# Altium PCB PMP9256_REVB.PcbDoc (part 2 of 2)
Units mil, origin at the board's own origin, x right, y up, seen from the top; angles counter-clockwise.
Board outline 5025 x 2070 mil, 4 copper layers (Top Layer, Signal Layer 1, Signal Layer 2, Bottom Layer), stack 61.2 mil thick; 115 components, 45 nets, 247 pads, 260 vias.
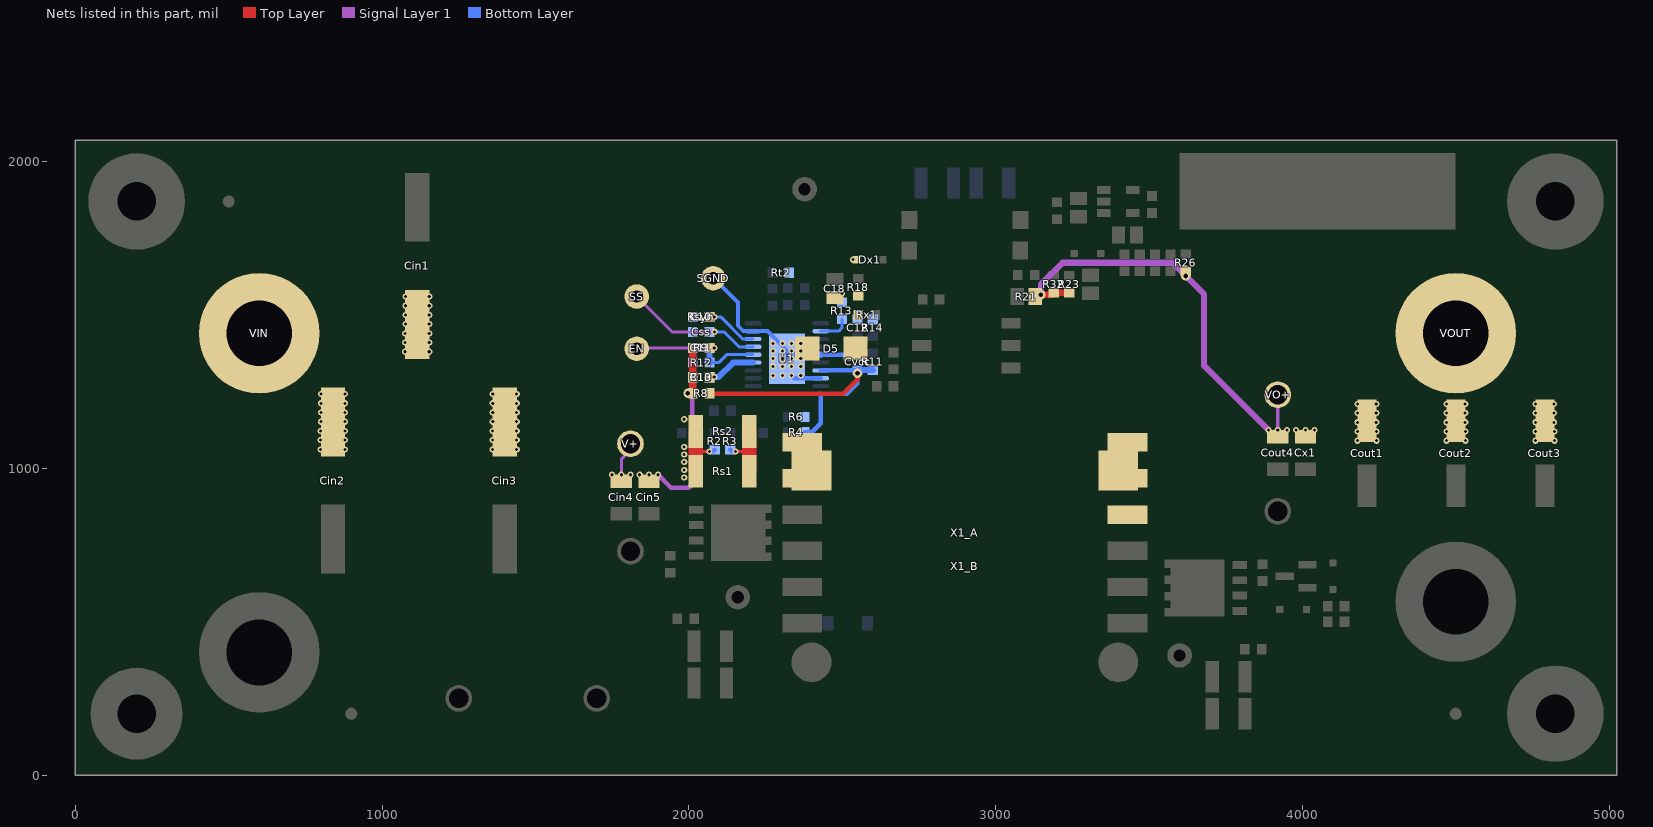
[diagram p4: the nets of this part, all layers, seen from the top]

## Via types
v1: diameter 20, hole 10, Top Layer to Bottom Layer, tented both sides, 252 vias
v2: diameter 30, hole 15, Top Layer to Bottom Layer, tented both sides, 8 vias

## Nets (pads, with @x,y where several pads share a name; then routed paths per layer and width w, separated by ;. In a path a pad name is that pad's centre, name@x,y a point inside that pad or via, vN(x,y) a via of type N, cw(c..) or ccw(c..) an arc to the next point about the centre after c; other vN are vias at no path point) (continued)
RS-: R3.2 Rs1.2 Rs2.2 X1_A.1 X1_A.2 X1_B.1 | length 181.7
  Top Layer w10: v1(2152,1055) 2196.61,1055
  Top Layer w47: Rs1.2@2196.61,990 2196.61,1055 Rs2.2@2196.61,1120
  Bottom Layer w15: R3.2@2135,1060 R3.2@2140,1055
SGND: C11.2 C12.2 C13.2 C18.2 Css.2 Cvcc.1 D5.2 Dx1.2 R6.1 R12.1 R13.1 R14.1 Rsyn.1 Rt2.1 SGND.1 U1.9 U1.15 U1.18 U1.21 | length 722
  Bottom Layer w12.5: SGND.1@2080,1620 2160,1540 2160,1464.6 2177.48,1447.13 U1.9@2209.76,1447.13 2256.17,1447.13 2320,1383.3 U1.21@2320,1357.56
  Bottom Layer w15: v1(2335,1302.56) 2343.98,1293.58 U1.18@2430.24,1293.58 ; U1.15@2430.44,1370.56 Cvcc.1@2550,1370.56
  Bottom Layer w20: U1.21@2335,1370.35 U1.15@2430.24,1370.35 U1.15@2430.44,1370.56
  other v1: 2275,1302.56 2305,1302.56 2365,1302.56 2275,1332.56 2305,1332.56 2335,1332.56 2365,1332.56 2275,1357.56 2305,1357.56 2335,1357.56 2365,1357.56 2275,1382.56 2305,1382.56 2335,1382.56 2365,1382.56 2275,1407.56 2305,1407.56 2335,1407.56 2365,1407.56 2500,1570 2535,1680
SLOPE: R13.2 U1.12 | length 101.9
  Bottom Layer w10: U1.12@2430.24,1447.13 2488.57,1447.13 2499.27,1457.83 R13.2@2499.27,1486.3
SS: Css.1 SS.1 U1.7 | length 464.2
  Signal Layer 1 w10: SS.1@1830,1560 1945.04,1444.96 v1(2084,1444.96)
  Bottom Layer w10: Css.1@2067.56,1444.96 v1(2084,1444.96) 2114.97,1444.96 2163.99,1395.94 U1.7@2209.76,1395.94
SYN/RT: C10.1 Rsyn.2 U1.8 | length 168.7
  Bottom Layer w10: Rsyn.2@2070.91,1493.56 2104,1493.56 2176.02,1421.54 U1.8@2209.76,1421.54
  other v1: 2084,1493.56
SYNC: U1.1
UVLO: C11.1 EN.1 R9.1 R12.2 U1.6 | length 469.6
  Signal Layer 1 w10: EN.1@1830,1390 1832.56,1392.56 v1(2083,1392.56)
  Bottom Layer w10: R12.2@2067.56,1344.56 2098,1344.56 2123.8,1370.35 U1.6@2209.76,1370.35 ; C11.1@2067.56,1392.56 v1(2083,1392.56)
  Bottom Layer w20: R12.2@2067.56,1344.56 C11.1@2067.56,1391.75
V+: Cin1.1 Cin2.1 Cin3.1 Cin4.1 Cin5.1 R2.2 R8.1 R9.2 R10.2 Rs1.1 Rs2.1 V+.1 VIN.1 | length 886.7
  Top Layer w10: 2023.39,1055 v1(2068,1055)
  Top Layer w25: R8.1@2012.44,1245 R10.2@2012.44,1296.56 R9.2@2012.44,1392.56
  Top Layer w47: Rs1.1@2023.39,990 2023.39,1055 Rs2.1@2023.39,1120
  Signal Layer 1 w10: v1(1780,979) 1780,1030 V+.1@1830,1080
  Signal Layer 1 w15: v1(1900,979) 1942,937 2000,937 2011,948 2011,1231 v2(1997,1245)
  Bottom Layer w15: R2.2@2080,1055 R2.2@2085,1060
  other v1: 1985,970 1750,979 1810,979 1840,979 1870,979 1985,995 1985,1020 1985,1045 800,1061.89 879,1061.89 1360,1061.89 1439,1061.89 1985,1070 800,1091.89 879,1091.89 1360,1091.89 1439,1091.89 800,1121.89 879,1121.89 1360,1121.89 1439,1121.89 801,1151.89 879,1151.89 1361,1151.89 1439,1151.89 1985.07,1160 801,1181.89 879,1181.89 1361,1181.89 1439,1181.89 801,1211.89 879,1211.89 1361,1211.89 1439,1211.89 801,1241.89 879,1241.89 1361,1241.89 1439,1241.89 1075,1380 1154,1380 1075,1410 1154,1410 1075,1440 1154,1440 1076,1470 1154,1470 1076,1500 1154,1500 1076,1530 1154,1530 1076,1560 1154,1560
VCC: Cvcc.2 D5.1 R4.2 R8.2 R11.2 R18.1 Rx1.2 U1.17 U1.20 | length 1031.3
  Top Layer w15: R8.2@2067.56,1245 2070.16,1242.4 2503.36,1242.4 2534.43,1273.47 2550,1289.04 v2(2550,1310)
  Bottom Layer w10: Cvcc.2@2550,1319.17 Cvcc.2@2550,1320
  Bottom Layer w13: U1.20@2430.24,1242.4 2515.84,1242.4 2550,1276.56 Cvcc.2@2550,1319.17
  Bottom Layer w15: R4.2@2377.56,1117.56 2401,1117.56 2430.24,1146.8 U1.20@2430.24,1242.4 ; U1.17@2430.24,1319.17 2534.43,1319.17 Cvcc.2@2550,1319.17
  Bottom Layer w20: Cvcc.2@2550,1320 R11.2@2600,1320
"VIN IC": C13.1 R10.1 U1.5 | length 157.8
  Bottom Layer w20: C13.1@2071.37,1297.89 2097.33,1297.89 2144.2,1344.76 U1.5@2209.76,1344.76
  other v1: 2083,1297.89
VOUT: Cout1.1 Cout2.1 Cout3.1 Cout4.1 Cx1.1 R21.2 R23.2 R26.2 R32.1 VO+.1 VOUT.1 X1_A.10 X1_A.11 X1_A.12 X1_B.4 | length 1396.3
  Top Layer w20: R21.2@3126.34,1573.31 3133.9,1565.75 v2(3147.81,1565.75) R32.1@3186.81,1565.75 ; R32.1@3190,1572.44 R23.2@3240,1572.44
  Signal Layer 1 w10: v1(3920,1124.5) VO+.1@3920,1240
  Signal Layer 1 w20: v2(3147.81,1565.75) 3147.81,1599.25 3218.56,1670 3577,1670 v2(3620,1627) 3680,1567 3680,1334.5 v1(3890,1124.5)
  other v1: 4180,1090 4242,1090 4470,1090 4532,1090 4760,1090 4822,1090 4180,1120 4242,1120 4470,1120 4532,1120 4760,1120 4822,1120 3950,1124.5 3980,1124.5 4010,1124.5 4040,1124.5 4180,1150 4241,1150 4470,1150 4531,1150 4760,1150 4821,1150 4180,1180 4241,1180 4470,1180 4531,1180 4760,1180 4821,1180 4180,1210 4241,1210 4470,1210 4531,1210 4760,1210 4821,1210
pads on no net: FID1.1 FID2.1 FID3.1 H1. H2. H3. H4. U3.1 U3.2 X2.2 X2.5

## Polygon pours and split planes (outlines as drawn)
SGND on Bottom Layer "Bottom Layer-SGND" (solid, pour order 22): 2070,1740 2575,1740 2640,1675 2640,1387.56 2400,1147.56 2050,1147.56 1980,1217.56 1980,1649.56
"ISO GND" on Bottom Layer "Bottom Layer-ISOGND" (solid, pour order 24): 5025,0 5025,2070 2960,2070 2960,0
PGND on Bottom Layer "Bottom Layer-PGND" (solid, remove dead copper, pour order 23): 0,2070 0,0 2840,0 2840,2070
Q1-D on Top Layer "Top Layer-Q1-D" (solid, pour order 30): 2840,900 2065,900 2065,0 2840,0
Q2-D on Top Layer "Top Layer-Q2-D" (solid, pour order 31): 3755,785 2960,785 2960,0 3755,0
RS- on Top Layer "Top Layer-RS-" (solid, pour order 27): 2840,1220 2840,910 2120,910 2120,1220
"ISO GND" on Top Layer "Top Layer-ISGND" (solid, pour order 35): 2960,2070 2960,1230.12 3553.12,1230.12 4043,1720 4685,1720 4870,1535 4870,1045 3890,1045 3765,920 3765,0 5025,0 5025,2070
VOUT on Top Layer "Top Layer-VOUT" (solid, pour order 29): 2960,1220 2960,795 3755,795 3755,925 3885,1055 4860.17,1055 4860.17,1529.83 4679.7,1710 4050,1710 3560,1220
V+ on Top Layer "Top Layer-VIN" (solid, pour order 26): 371,1551 371,910 2090,910 2090,1220 1760,1220 1270,1710 530,1710
PGND on Top Layer "Top Layer-PGND" (solid, pour order 33): 2840,2070 2840,1229.76 1765.24,1229.76 1275,1720 525,1720 360,1555 360,900 2055,900 2055,0 0,0 0,2070
VCC on Top Layer "Top Layer-VCC" (solid, pour order 36): 2570,1580 2530,1580 2530,1470 2500,1440 2500,1320 2510,1310 2520,1300 2550,1300 2570,1300 2590,1320 2590,1450 2570,1470
"ISO GND" on Signal Layer 2 "MidLayer2-ISOGND" (solid, pour order 21): 2960,0 5025,0 5025,2070 2960,2070
PGND on Signal Layer 2 "MidLayer2-PGND" (solid, pour order 20): 0,0 0,2070 2840,2070 2840,0
"ISO GND" on Signal Layer 1 "MidLayer1-ISGND" (solid, pour order 34): 2960,2070 2960,1230.12 3553.12,1230.12 4043,1720 4685,1720 4870,1535 4870,1045 3890,1045 3765,920 3765,785 2960,785 2960,0 5025,0 5025,2070
VOUT on Signal Layer 1 "MidLayer1-VOUT" (solid, pour order 28): 2960,1220 2960,795 3755,795 3755,925 3885,1055 4860.17,1055 4860.17,1529.83 4679.7,1710 4050,1710 3560,1220
V+ on Signal Layer 1 "MidLayer1-VIN" (solid, pour order 25): 370,1550 370,910 2840,910 2840,1220 1760,1220 1270,1710 530,1710
PGND on Signal Layer 1 "MidLayer1-PGND" (solid, pour order 32): 2840,2070 2840,1229.76 1765.24,1229.76 1275,1720 525,1720 360,1555 360,900 2840,900 2840,0 0,0 0,2070

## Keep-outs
Keep-Out Layer:
  the board outline again, w10
  text ".Layer_Name" at 577,-858.49 h60

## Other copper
Top Layer:
  pour cut-out: 2152,1038.37 2152,1071.63 2174,1071.63 2174,1038.37
  pour cut-out: 2068,1071.63 2068,1038.37 2046,1038.37 2046,1071.63
  pour cut-out: 360,910 360,900 2055,900 2055,0 2065,0 2065,900 2895,900 2895,0 2905,0 2905,785 3755,785 3755,0 3765,0 3765,920 3890,1045 4870,1045 4870,1055.02 3885,1055 3755,925 3755,795 2905,795 2905,1220 2895,1220 2895,910 2120,910 2120,1220 3560,1220 4050,1710 4679.7,1710 4860.17,1529.83 4860,1055 4870,1055 4870,1535 4685,1720 4043,1720 3553.43,1230.43 2905,1230 2905,2070 2895,2070 2895,1230.23 2110,1230 1765,1230 1275,1720 525,1720 360,1555 360,910 370,910 370,1550 530,1710 1270,1710 1760,1220 2100,1220 2100,910
  pour cut-out: 2135.69,1055 ccw(c2152,1055) 2152,1038.69 ccw(c2152,1055) 2168.31,1055 ccw(c2152,1055) 2152,1071.31 ccw(c2152,1055)
  pour cut-out: 2051.69,1055 ccw(c2068,1055) 2068,1038.69 ccw(c2068,1055) 2084.31,1055 ccw(c2068,1055) 2068,1071.31 ccw(c2068,1055)
  pour cut-out: 1760.46,1079.61 ccw(c1810.39,1079.61) 1810.39,1029.68 ccw(c1810.39,1079.61) 1860.32,1079.61 ccw(c1810.39,1079.61) 1810.39,1129.53 ccw(c1810.39,1079.61)
  pour cut-out: 1759.68,730.39 ccw(c1809.61,730.39) 1809.61,680.46 ccw(c1809.61,730.39) 1859.53,730.39 ccw(c1809.61,730.39) 1809.61,780.32 ccw(c1809.61,730.39)
  pour cut-out: 3870.07,1240 ccw(c3920,1240) 3920,1190.07 ccw(c3920,1240) 3969.93,1240 ccw(c3920,1240) 3920,1289.93 ccw(c3920,1240)
  pour cut-out: 3870.07,860 ccw(c3920,860) 3920,810.07 ccw(c3920,860) 3969.93,860 ccw(c3920,860) 3920,909.93 ccw(c3920,860)
  text ".CopyrightYear" at 4070,70 h60
  text "TI" at 4346,70 h60
  text "©" at 3953,66.48 h105
  text ".Layer_Name" at 577,-858.49 h60
Signal Layer 1:
  pour cut-out: 360,910 360,900 2895,900 2895,0 2905,0 2905,785 3765,785 3765,920 3890,1045 4870,1045 4870,1055.02 3885,1055 3755,925 3755,795 2905,795 2905,1220 3560,1220 4050,1710 4679.7,1710 4860.17,1529.83 4860,1055 4870,1055 4870,1535 4685,1720 4043,1720 3553,1230 1765,1230 1275,1720 525,1720 360,1555 360,910 370,910 370,1550 530,1710 1270,1710 1760,1220 2895,1220 2895,910
  pour cut-out: 2905,2070 2905,0 2895,0 2895,2070
  pour cut-out: 2051.69,1055 ccw(c2068,1055) 2068,1038.69 ccw(c2068,1055) 2084.31,1055 ccw(c2068,1055) 2068,1071.31 ccw(c2068,1055)
  pour cut-out: 1883.37,979 ccw(c1900,979) 1900,962.37 ccw(c1900,979) 1916.63,979 ccw(c1900,979) 1900,995.63 ccw(c1900,979)
  pour cut-out: 3936.11,1124.5 ccw(c3920,1124.5) 3920,1140.61 ccw(c3920,1124.5) 3903.89,1124.5 ccw(c3920,1124.5) 3920,1108.39 ccw(c3920,1124.5)
  pour cut-out: 3936.31,974.5 ccw(c3920,974.5) 3920,990.81 ccw(c3920,974.5) 3903.69,974.5 ccw(c3920,974.5) 3920,958.19 ccw(c3920,974.5)
  pour cut-out: 1760.46,1079.61 ccw(c1810.39,1079.61) 1810.39,1029.68 ccw(c1810.39,1079.61) 1860.32,1079.61 ccw(c1810.39,1079.61) 1810.39,1129.53 ccw(c1810.39,1079.61)
  pour cut-out: 1763.69,979 ccw(c1780,979) 1780,962.69 ccw(c1780,979) 1796.31,979 ccw(c1780,979) 1780,995.31 ccw(c1780,979)
  pour cut-out: 1763.69,831 ccw(c1780,831) 1780,814.69 ccw(c1780,831) 1796.31,831 ccw(c1780,831) 1780,847.31 ccw(c1780,831)
  pour cut-out: 1759.68,730.39 ccw(c1809.61,730.39) 1809.61,680.46 ccw(c1809.61,730.39) 1859.53,730.39 ccw(c1809.61,730.39) 1809.61,780.32 ccw(c1809.61,730.39)
  pour cut-out: 3870.07,1240 ccw(c3920,1240) 3920,1190.07 ccw(c3920,1240) 3969.93,1240 ccw(c3920,1240) 3920,1289.93 ccw(c3920,1240)
  pour cut-out: 3870.07,860 ccw(c3920,860) 3920,810.07 ccw(c3920,860) 3969.93,860 ccw(c3920,860) 3920,909.93 ccw(c3920,860)
Signal Layer 2:
  rectangle net PGND: 2220,1230 2423.73,1480
  rectangle net SGND: 2258,1265.16 2388,1452.16
  pour cut-out: 2895,2070 2905,2070 2905,0 2895,0
Bottom Layer:
  rectangle net ISO: 2840,1877 2960,1982
  pour cut-out: 2895,2070 2905,2070 2905,0 2895,0
  pour cut-out: 1970,1655 1970,1212.56 2045.14,1137.42 2400,1137.62 2400,1147.56 2050,1147.56 1980,1217.56 1980,1650 2070,1740 2575,1740 2640,1675 2640,1387.56 2400,1147.56 2400,1137.63 2650,1383.32 2650,1680 2580,1750 2065,1750
  pour cut-out: 2345,1515.56 2397.43,1515.56 2397.43,1415.56 2386,1415.56 2386,1506.83 2345,1506.83
  text ".Layer_Name" at 577,-858.49 h60

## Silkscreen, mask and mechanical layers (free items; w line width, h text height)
Top Overlay:
  text ".PRJ_Number" at 1500,1890 h60
  text ".PCB_Rev" at 2100,1890 h60
  text ".PRJ_Title" at 1800,60 h60
  text ".Layer_Name" at 577,-858.49 h60
Bottom Overlay:
  rectangle: 2410,830 2710,930
  text ".PRJ_Number" at 3377,851 h60
  text "-" at 2790,850 h60
  text ".PCB_Rev" at 2890,850 h60
  text "UL94V-0" at 119,495 h60 r270
  text "MADE IN U.S." at 4550,83 h60
  text ".Layer_Name" at 577,-858.49 h60
Top Paste:
  text ".Layer_Name" at 577,-858.49 h60
Bottom Paste:
  text ".Layer_Name" at 577,-858.49 h60
Top Solder:
  text ".Layer_Name" at 577,-858.49 h60
  text ".Layer_Name" at 577,-858.49 h60
Bottom Solder:
  text ".Layer_Name" at 577,-858.49 h60
Drill Guide:
  text ".Layer_Name" at 577,-858.49 h60
M1 Board Outline:
  the board outline again, w10
  text ".Layer_Name" at 577,-858.49 h60
M2 Board Dimensions:
  rectangle: 0,-275 125,-150
  rectangle: 125,-400 500,-275
  lines w7: 0,-275 1000,-275 ; 125,-400 125,-150 ; 250,-400 250,-150 ; 500,-400 500,-150 ; 750,-400 750,-150 ; 0,-400 1000,-400 1000,-150 0,-150 0,-400
  text ".Layer_Name" at 577,-858.49 h60
M3 3D STEP Top:
  text ".Layer_Name" at 577,-858.49 h60
M4 3D STEP Bottom:
  text ".Layer_Name" at 577,-858.49 h60
M5 Assembly Top:
  lines w10: -292,-930.17 6308,-930.17 ; -292,-726.83 6310,-726.83 ; -292,-523.5 -292,-1133.5 3713,-1133.5 6310,-1133.5 6310,-523.5 -291.5,-523.5 -291.5,-1133.5 1284,-1133.5 ; 2173,-1133.5 2173,-523.5 ; 3440,-726.83 3440,-523.5 ; 4280,-726.83 4280,-523.5 ; 4902,-1140 4902,-937.17
  text "COMPONENTS MARKED 'DNP' SHOULD NOT BE POPULATED." at 1153.5,-318.5 h60
  text "ASSEMBLY VARIANT:" at 1153,-434 h60
  text ".VariantName" at 2189,-434 h60
  text "PCB VIEWED FROM TOP SIDE" at -228.5,-655.67 h60
  text "BOARD #:" at 2248,-655.67 h60
  text ".PRJ_Number" at 2793.5,-655.67 h60
  text "REV:" at 3638,-655.67 h60
  text ".PCB_Rev" at 3929.5,-655.67 h60
  text "SVN REV:" at 4476,-655.67 h60
  text ".VersionControl_RevNumber" at 4982,-655.67 h60
  text "PLOT NAME =" at -228.5,-1064.34 h60
  text ".plot_File_Name" at 577,-1064.34 h60
  text "GENERATED    :" at 2250,-1064.34 h60
  text ".Print_Date" at 3119.5,-1064.34 h60
  text ".Print_Time" at 3848.5,-1064.34 h60
  text "TEXAS INSTRUMENTS" at 5113,-1064.34 h60
M6 Assembly Bottom:
  lines w10: -292.5,-727.33 6309.5,-727.33 ; -290.5,-930.67 6309.5,-930.67 ; 1115.5,-1140.5 1115.5,-937.67 ; 1737.5,-727.33 1737.5,-524 ; 2577.5,-727.33 2577.5,-524 ; 3844.5,-1134 3844.5,-524 ; 4733.5,-1134 6309,-1134 6309,-524 -292.5,-524 -292.5,-1134 2304.5,-1134 6309.5,-1134 6309.5,-524
  text "COMPONENTS MARKED 'DNP' SHOULD NOT BE POPULATED." at 6102,-318 h60
  text ".VariantName" at 5058,-434 h60
  text "ASSEMBLY VARIANT:" at 6097,-434 h60
  text ".VersionControl_RevNumber" at 1035.5,-656.17 h60
  text "SVN REV:" at 1541.5,-656.17 h60
  text ".PCB_Rev" at 2088,-656.17 h60
  text "REV:" at 2379.5,-656.17 h60
  text ".PRJ_Number" at 3224,-656.17 h60
  text "BOARD #:" at 3769.5,-656.17 h60
  text "PCB VIEWED FROM BOTTOM SIDE" at 6246,-656.17 h60
  text "TEXAS INSTRUMENTS" at 904.5,-1064.84 h60
  text ".Print_Time" at 2169,-1064.84 h60
  text ".Print_Date" at 2898,-1064.84 h60
  text "GENERATED    :" at 3767.5,-1064.84 h60
  text ".plot_File_Name" at 5440.5,-1064.84 h60
  text "PLOT NAME =" at 6246,-1064.84 h60
M9 Title Sheet:
  drawing of 57 lines, arcs and shapes, not listed
  text "1" at 739.84,8036.5 h70
  text "2" at 3235.5,8036.5 h70
  text "3" at 5724.84,8036.5 h70
  text "4" at 8231.51,8036.5 h70
  text "5" at 10730.5,8036.5 h70
  text "6" at 13235.5,8036.5 h70
  text "A" at -416.5,6893.5 h70
  text "A" at 14383.5,6893.5 h70
  text "B" at -416.5,4513.5 h70
  text "B" at 14383.5,4513.5 h70
  text "C" at -416.5,2138.5 h70
  text "C" at 14383.5,2138.5 h70
  text "PROJECT TITLE:" at 11343.5,277.5 h45
  text ".PRJ_Title" at 11393.5,144.17 h70
  text "DESIGNED FOR:" at 11343.5,-23.5 h45
  text ".PRJ_Customer" at 11393.5,-163.5 h70
  text "D" at -416.5,-231.5 h70
  text "D" at 14383.5,-231.5 h70
  text "FILE NAME:" at 11343.5,-323.5 h45
  text ".PCB_File_Name_No_Path" at 11393.5,-443.5 h70
  text "Texas Instruments (TI) and/or its licensors do not warrant the accuracy or completeness of this specification" at 6374,-605.34 h45
  text "ENGINEER:" at 11343.5,-613.5 h45
  text "LAYOUT BY:" at 12848.5,-613.5 h45
  text "or any information contained therein. TI and/or its licensors do not warrant that this design will meet" at 6329.01,-718 h45
  text ".PRJ_Engineer" at 11393.5,-768.49 h70
  text ".PCB_Layout" at 12899,-768.49 h70
  text "the specifications, will be suitable for your application or fit for any particular purpose, or will operate in" at 6329.01,-830.67 h45
  text ".Layer_Name" at 577,-858.49 h60
  text "ALTIUM DESIGNER VERSION:" at 12848.5,-923.5 h45
  text "an implementation. TI and/or its licensors do not warrant that the design is production worthy. You should" at 6329.01,-943.33 h45
  text "completely validate and test your design implementation to confirm the system functionality for your application." at 6374,-1056 h45
  text ".print_Scale" at 11393.5,-1056.83 h70
  text ".Application_BuildNumber" at 12899,-1056.83 h70
  text "1" at 739.84,-1263.5 h70
  text "2" at 3235.5,-1263.5 h70
  text "3" at 5724.84,-1263.5 h70
  text "4" at 8231.51,-1263.5 h70
  text "5" at 10730.5,-1263.5 h70
  text "6" at 13235.5,-1263.5 h70
M10 Fab Notes:
  drawing of 185 lines, arcs and shapes, not listed
  text "DESIGN INFORMATION" at 12381.02,5910 h60
  text "MIN. TRACK WIDTH:" at 11736.46,5730 h60
  text "8" at 12832.7,5730 h60
  text "MIL" at 12987.46,5730 h60
  text "MIN. CLEARANCE:" at 11736.46,5598 h60
  text "0.2" at 12772.7,5598 h60
  text "mm" at 12987.46,5598 h60
  text "MIN. VIA PAD SIZE:" at 11736.46,5466 h60
  text "20" at 12802.71,5466 h60
  text "MIL" at 12987.46,5466 h60
  text "0.05mm (2MIL)" at 12431.46,5324.29 h60
  text "MINIMUM ANNULAR RING" at 11407.23,5320 h60
  text "EXTERNAL" at 13139.46,5320 h60
  text "PER" at 11607.23,5202 h60
  text "IPC-D-275 CLASS 2 LEVEL C" at 11827.23,5202 h60
  text "MIL, HOLES" at 13315.46,5089.71 h60
  text "+/-" at 12923,5089 h60
  text "+/-" at 13777,5089 h60
  text "REGISTRATION TOLERANCES:" at 11407.23,5084 h60
  text "METAL" at 12607,5084 h60
  text "5" at 13183.2,5084 h60
  text "3" at 14016.2,5084 h60
  text "MIL" at 14132.46,5084 h60
  text "MATERIAL:" at 11332.46,4874.54 h60
  text "FR-4 High Tg" at 12318.9,4734.21 h60
  text "FR-408" at 11753.46,4725.64 h60
  text "OTHER" at 13241.46,4725.64 h60
  text "X" at 12160,4720 h60
  text "62 MIL (1.6mm) +/-10%" at 12073.56,4562.92 h60
  text "THICKNESS:" at 11407.23,4558.64 h60
  text "X" at 11945.4,4558.64 h60
  text "OTHER" at 13358.46,4558.64 h60
  text "TOLERANCE:" at 11407.23,4400.64 h60
  text "X" at 12246.53,4400.64 h60
  text "ANSI IPC-6012 TYPE 3 CLASS 2" at 12433.48,4400.64 h60
  text "OTHER +/-" at 12433.46,4244.64 h60
  text "BOW & TWIST:" at 11407.23,4087.64 h60
  text "X" at 12246.53,4087.64 h60
  text "ANSI IPC-6012 TYPE 3 CLASS 2" at 12433.48,4087.64 h60
  text "OTHER +/-" at 12433.46,3929.13 h60
  text "DRILLING:" at 11332.46,3790.64 h60
  text "REFERENCE:" at 11407.23,3673.64 h60
  text "X" at 12055.46,3673.64 h60
  text "AS SHOWN" at 12242.46,3673.64 h60
  text "X" at 12956.46,3673.64 h60
  text "NC_DRILL FILES" at 13093.46,3673.64 h60
  text "PTH MIN COPPER THICKNESS:" at 11407.23,3515.64 h60
  text "X" at 12757.46,3515.64 h60
  text "1MIL" at 12894.46,3515.64 h60
  text "OTHER" at 13391.46,3515.64 h60
  text "BOARD FINISH:" at 11332.46,3356.64 h60
  text "SILKSCREEN:" at 11487.68,3238.64 h60
  text "X" at 12436.46,3238.64 h60
  text "TOP" at 12562.46,3238.64 h60
  text "X" at 12946.46,3238.64 h60
  text "BOTTOM" at 13073.46,3238.64 h60
  text "SILKSCREEN COLOR:" at 11487.68,3071.64 h60
  text "X" at 12435.42,3071.64 h60
  text "WHITE" at 12562.46,3071.64 h60
  text "OTHER" at 13073.46,3071.64 h60
  text "SOLDER RESIST COLOR:" at 11487.68,2901.64 h60
  text "X" at 12055.42,2742.44 h60
  text "GREEN" at 12182.46,2742.44 h60
  text "BLUE" at 12773.46,2742.44 h60
  text "OTHER" at 13311.46,2742.44 h60
  text "IMMERSION GOLD (ENIG)" at 12393.46,2553.92 h60
  text "ENEPIG" at 13731,2550.64 h60
  text "SURFACE FINISH:" at 11332.46,2549.64 h60
  text "IMM. TIN/SILVER OR EQUIV" at 11662,2392.64 h60
  text "OTHER" at 13093.46,2392.64 h60
  text "X" at 11500,2390 h60
  text "ARRAY/PANEL:" at 11332.46,2213.64 h60
  text "X" at 12210,2210 h60
  text "CUT AND TRIM PER MECH LAYER 1" at 12393.46,2209.35 h60
  text "N.C. ROUTE" at 12393.46,2057.64 h60
  text "V. SCORE" at 13259.46,2057.64 h60
  text "CERTIFICATION:" at 11332.46,1920.64 h60
  text "MATERIALS AND WORKMANSHIP FOR ALL PCBS" at 12057.46,1920.64 h60
  text "TO MEET OR EXCEED THE REQUIREMENTS OF:" at 12057.46,1822.64 h60
  text "X" at 11683.96,1686.13 h60
  text "ANSI IPC-A-600F CLASS ->" at 11822.96,1686.13 h60
  text "X" at 13462.02,1686.13 h60
  text "2" at 13580.96,1686.14 h60
  text "1" at 13265.96,1684.64 h60
  text "3" at 13934.96,1684.64 h60
  text "X" at 11686.02,1526.64 h60
  text "UL 94V-0" at 11822.96,1526.64 h60
  text "X" at 12498.02,1526.64 h60
  text "RoHS" at 12634.96,1526.64 h60
  text "OTHER" at 13279.36,1526.64 h60
  text "PER ORDER" at 13676.42,1526.64 h60
  text "ADDITIONAL REQUIREMENTS:" at 11332.46,1385.64 h60
  text "MICROSECTION:" at 11407.23,1270.64 h60
  text "YES" at 12312.96,1270.64 h60
  text "REQUIRED" at 13174.46,1114.49 h60
  text "BARE BOARD ELEC. TEST:" at 11407.23,1111.64 h60
  text "NONE" at 12712.96,1111.64 h60
  text "PER ORDER" at 13766.46,1111.64 h60
  text "X" at 12590,1110 h60
  text "MANUFACTURER'S UL:" at 11407.23,954.64 h60
  text "RAIL" at 12572.96,950.35 h60
  text "METAL" at 13064.77,950.35 h60
  text "X" at 13440,950 h60
  text "SILK" at 13576.46,950.35 h60
  text ".Layer_Name" at 577,-858.49 h60
M11 Gerber Information:
  lines w10: -292,-930.17 6308,-930.17 ; -292,-726.83 6310,-726.83 ; -292,-523.5 -292,-1133.5 3713,-1133.5 6310,-1133.5 6310,-523.5 -291.5,-523.5 -291.5,-1133.5 1284,-1133.5 ; 2173,-1133.5 2173,-523.5 ; 3440,-726.83 3440,-523.5 ; 4280,-726.83 4280,-523.5 ; 4902,-1140 4902,-937.17
  text "ALL ARTWORK VIEWED FROM TOP SIDE" at -228.5,-655.67 h60
  text "BOARD #:" at 2248,-655.67 h60
  text ".PRJ_Number" at 2793.5,-655.67 h60
  text "REV:" at 3638,-655.67 h60
  text ".PCB_Rev" at 3929.5,-655.67 h60
  text "SVN REV:" at 4476,-655.67 h60
  text ".VersionControl_RevNumber" at 4982,-655.67 h60
  text "LAYER NAME =" at -228.5,-858.49 h60
  text "PLOT NAME =" at -228.5,-1064.34 h60
  text ".plot_File_Name" at 577,-1064.34 h60
  text "GENERATED    :" at 2250,-1064.34 h60
  text ".Print_Date" at 3119.5,-1064.34 h60
  text ".Print_Time" at 3848.5,-1064.34 h60
  text "TEXAS INSTRUMENTS" at 5113,-1064.34 h60
M12 Stackup:
  drawing of 295 lines, arcs and shapes, not listed
  text "Layer" at 9790.58,7830 h60
  text "Name" at 10200.49,7830 h60
  text "Material" at 11140.23,7830 h60
  text "Thickness" at 12000,7830 h60
  text "Constant" at 12649.83,7830 h60
  text "Board Layer Stack" at 13219.69,7830 h60
  text "1" at 9790.58,7710 h60
  text "Top Overlay" at 10200.49,7710 h60
  text "2" at 9790.58,7590 h60
  text "Top Solder" at 10200.49,7590 h60
  text "Solder Resist" at 11140.23,7590 h60
  text "0.40mil" at 12000,7590 h60
  text "3.5" at 12649.83,7590 h60
  text "3" at 9790.58,7470 h60
  text "Top Layer" at 10200.49,7470 h60
  text "Copper" at 11140.23,7470 h60
  text "1.40mil" at 12000,7470 h60
  text "4" at 9790.58,7350 h60
  text "Dielectric1" at 10200.49,7350 h60
  text "FR-4" at 11140.23,7350 h60
  text "10.00mil" at 12000,7350 h60
  text "4.8" at 12649.83,7350 h60
  text "5" at 9790.58,7230 h60
  text "Signal Layer 1" at 10200.49,7230 h60
  text "Copper" at 11140.23,7230 h60
  text "0.70mil" at 12000,7230 h60
  text "6" at 9790.58,7110 h60
  text "Dielectric 3" at 10200.49,7110 h60
  text "FR-4" at 11140.23,7110 h60
  text "37.00mil" at 12000,7110 h60
  text "4.2" at 12649.83,7110 h60
  text "7" at 9790.58,6990 h60
  text "Signal Layer 2" at 10200.49,6990 h60
  text "Copper" at 11140.23,6990 h60
  text "0.70mil" at 12000,6990 h60
  text "8" at 9790.58,6870 h60
  text "Dielectric 2" at 10200.49,6870 h60
  text "FR-4" at 11140.23,6870 h60
  text "10.00mil" at 12000,6870 h60
  text "4.2" at 12649.83,6870 h60
  text "9" at 9790.58,6750 h60
  text "Bottom Layer" at 10200.49,6750 h60
  text "Copper" at 11140.23,6750 h60
  text "1.40mil" at 12000,6750 h60
  text "10" at 9790.58,6630 h60
  text "Bottom Solder" at 10200.49,6630 h60
  text "Solder Resist" at 11140.23,6630 h60
  text "0.40mil" at 12000,6630 h60
  text "3.5" at 12649.83,6630 h60
  text "11" at 9790.58,6510 h60
  text "Bottom Overlay" at 10200.49,6510 h60
  text ".Layer_Name" at 577,-858.49 h60
M13 Component Bodies Top:
  text ".Layer_Name" at 577,-858.49 h60
M14 Component Bodies Bottom:
  text ".Layer_Name" at 577,-858.49 h60
M15 Courtyards Top:
  text ".Layer_Name" at 577,-858.49 h60
M16 Courtyards Bottom:
  text ".Layer_Name" at 577,-858.49 h60
Drill Drawing:
  circle w1: c5572.72,3221.04 r24.89
  lines w1: 5547.83,2449.56 5547.83,2462 5560.27,2474.44 5547.83,2486.89 5547.83,2499.33 5560.27,2499.33 5572.72,2486.89 5585.16,2499.33 5597.6,2499.33 5597.6,2486.89 5585.16,2474.44 5597.6,2462 5597.6,2449.56 5585.16,2449.56 5572.72,2462 5560.27,2449.56 5547.83,2449.56 ; 5547.83,2598.88 5597.6,2598.88 5597.6,2648.65 5547.83,2648.65 5547.83,2598.88 ; 5547.83,2760.64 5560.27,2760.64 5560.27,2748.2 5585.16,2748.2 5585.16,2760.64 5597.6,2760.64 5597.6,2785.53 5585.16,2785.53 5585.16,2797.97 5560.27,2797.97 5560.27,2785.53 5547.83,2785.53 5547.83,2760.64 ; 5547.83,2897.52 5572.72,2909.96 5597.6,2897.52 5585.16,2922.4 5597.6,2947.29 5572.72,2934.85 5547.83,2947.29 5560.27,2922.4 5547.83,2897.52 ; 5547.83,3059.28 5560.27,3059.28 5572.72,3046.84 5585.16,3059.28 5597.6,3059.28 5585.16,3071.72 5597.6,3084.17 5585.16,3084.17 5572.72,3096.61 5560.27,3084.17 5547.83,3084.17 5560.27,3071.72 5547.83,3059.28
  lines w12: 5480,2404.76 7598.02,2404.76 ; 5480,3300.68 7598.02,3300.68 ; 5850.36,2255.44 5850.36,3450 ; 6207.36,2255.44 6207.36,3450 ; 6868.93,2255.44 6868.93,3450 ; 7153.07,2255.44 7153.07,3450 ; 5480,2255.44 7598.02,2255.44 7598.02,3450 5480,3450 5480,2255.44
  text "Symbol" at 5569.59,3345.48 h72
  text "Quantity" at 5895.16,3345.48 h72
  text "Finished Hole Size" at 6252.16,3345.48 h72
  text "Plated" at 6913.72,3345.48 h72
  text "Hole Type" at 7197.86,3345.48 h72
  text "252" at 5895.16,3196.16 h60
  text "10.00mil (0.254mm)" at 6252.16,3196.16 h60
  text "PTH" at 6913.72,3196.16 h60
  text "Round" at 7197.86,3196.16 h60
  text "8" at 5895.16,3046.84 h60
  text "15.00mil (0.381mm)" at 6252.16,3046.84 h60
  text "PTH" at 6913.72,3046.84 h60
  text "Round" at 7197.86,3046.84 h60
  text "6" at 5895.16,2897.52 h60
  text "40.00mil (1.016mm)" at 6252.16,2897.52 h60
  text "PTH" at 6913.72,2897.52 h60
  text "Round" at 7197.86,2897.52 h60
  text "6" at 5895.16,2748.2 h60
  text "63.00mil (1.600mm)" at 6252.16,2748.2 h60
  text "PTH" at 6913.72,2748.2 h60
  text "Round" at 7197.86,2748.2 h60
  text "4" at 5895.16,2598.88 h60
  text "125.98mil (3.200mm)" at 6252.16,2598.88 h60
  text "PTH" at 6913.72,2598.88 h60
  text "Round" at 7197.86,2598.88 h60
  text "4" at 5895.16,2449.56 h60
  text "214.57mil (5.450mm)" at 6252.16,2449.56 h60
  text "PTH" at 6913.72,2449.56 h60
  text "Round" at 7197.86,2449.56 h60
  text "280 Total" at 5895.16,2300.24 h60
  text ".Layer_Name" at 577,-858.49 h60

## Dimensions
0,-400 to 1000,-400 on M2 Board Dimensions
0,0 to 5025,0 on M2 Board Dimensions
0,0 to 0,2070 on M2 Board Dimensions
